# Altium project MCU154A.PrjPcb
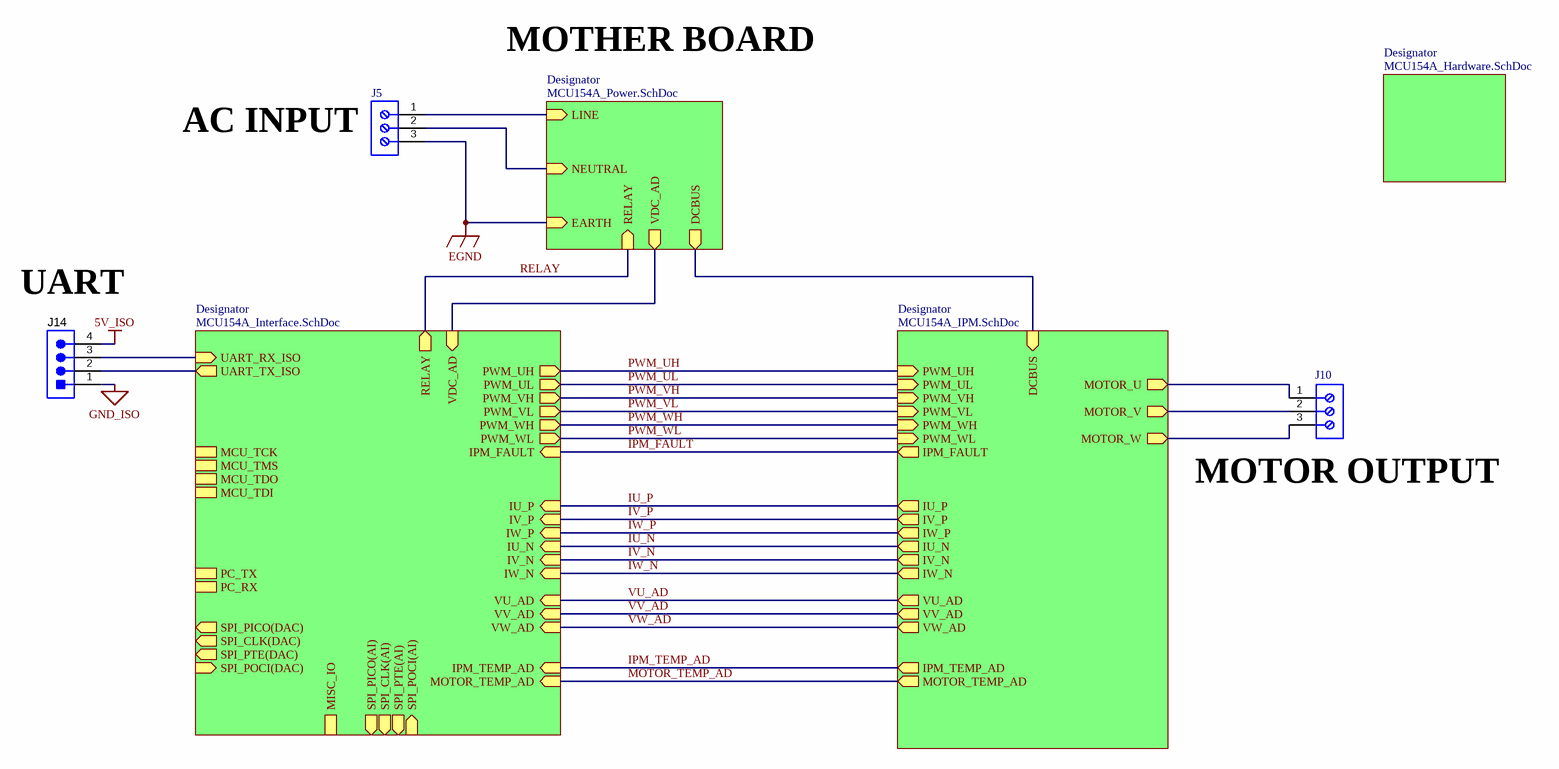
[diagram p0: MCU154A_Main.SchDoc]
CopyrightYear: 2024; EVM_orderable: TIEVM-MTR-HVIVN; Input_F: 50 Hz; Input_I: 8 A; Input_V: 230 VAC; Output_F_Motor: 200 Hz; Output_I: 3 A; Output_P: 750 W; Output_V: not available; PCB_Rev: A; PRJ_Customer: Public Release; PRJ_Engineer: Jason Osborn; PRJ_Number: MCU154; PRJ_Title: TIEVM-MTR-HVINV; SCH_Rev: A; TechSupport: http://www.ti.com/support; TID: TIDA-010265
5 sheets, 179 parts. Net scope: hierarchical (ports join the sheet entries above them; power ports are global).
Board file: MCU154A_PCB.PcbDoc
Sheets:
  MCU154A_Main.SchDoc
    Designator = MCU154A_Power.SchDoc
    Designator = MCU154A_IPM.SchDoc
    Designator = MCU154A_Interface.SchDoc
    Designator = MCU154A_Hardware.SchDoc

## Sheet MCU154A_Main.SchDoc: Main
size A3; Date: Not shown in title block; ApprovedBy: Not shown in title block; CheckedBy: Not shown in title block; Author: Not shown in title block; CompanyName: Not shown in title block; DrawnBy: Hely Zhang; Engineer: Not shown in title block; Organization: Not shown in title block; Address1: Not shown in title block; Address2: Not shown in title block; Address3: Not shown in title block; Address4: Not shown in title block; DocumentNumber: 1; Revision: Use project parameter SCH_Rev; SheetNumber: 1; SheetTotal: 5; PageSetup: Record=PageOptions¦CenterHorizontal=True¦CenterVertical=True¦PrintScale=0.93¦XCorrection=1.00¦YCorrection=1.00¦PrintKind=0¦BorderSize=5000000¦LeftOffset=0¦BottomOffset=0¦Orientation=2¦PaperLength=1000¦PaperWidth=1000¦Scale=100¦PaperSource=15¦PrintQuality=600¦MediaType=1¦DitherType=10¦PaperKind=Letter¦PrintScaleMode=1

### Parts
J5  691137710003  [691137710003]  (value not drawn)
J10  691137710003  [691137710003]  (value not drawn)
J14  70543-0038  [Molex_70543-0038]  (value not drawn)

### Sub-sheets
Designator = MCU154A_Power.SchDoc: RELAY (in), DCBUS (out), EARTH (in), LINE (in), NEUTRAL (in), VDC_AD (out)
Designator = MCU154A_IPM.SchDoc: MOTOR_U (out), MOTOR_V (out), VU_AD (out), VV_AD (out), VW_AD (out), PWM_UL (in), PWM_VH (in), PWM_VL (in), PWM_WH (in), PWM_WL (in), PWM_UH (in), IPM_FAULT (out), IW_P (out), IU_P (out), IV_P (out), MOTOR_TEMP_AD (out), DCBUS (in), MOTOR_W (out), IPM_TEMP_AD (out), IW_N (out), IU_N (out), IV_N (out)
Designator = MCU154A_Interface.SchDoc: PWM_UH (out), PWM_UL (out), PWM_VH (out), PWM_VL (out), PWM_WH (out), PWM_WL (out), RELAY (out), IV_P (in), IW_P (in), VU_AD (in), VV_AD (in), VW_AD (in), IPM_TEMP_AD (in), MOTOR_TEMP_AD (in), VDC_AD (in), SPI_PICO(DAC) (out), SPI_CLK(DAC) (out), SPI_POCI(DAC) (in), PC_RX, PC_TX, SPI_PTE(AI) (out), SPI_CLK(AI) (out), SPI_POCI(AI) (in), SPI_PICO(AI) (out), MCU_TCK, MCU_TMS, IPM_FAULT (in), IW_N (in), IU_N (in), IU_P (in), MISC_IO, IV_N (in), MCU_TDI, MCU_TDO, SPI_PTE(DAC) (out), UART_RX_ISO (in), UART_TX_ISO (out)
Designator = MCU154A_Hardware.SchDoc: no entries

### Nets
5V_ISO: J14.4
EGND: J5.3 ; sheet Designator/EARTH
GND_ISO: J14.1
Ubus: sheet Designator/DCBUS, sheet Designator/DCBUS
IPM_FAULT: sheet Designator/IPM_FAULT, sheet Designator/IPM_FAULT
IPM_TEMP_AD: sheet Designator/IPM_TEMP_AD, sheet Designator/IPM_TEMP_AD
IU_N: sheet Designator/IU_N, sheet Designator/IU_N
IU_P: sheet Designator/IU_P, sheet Designator/IU_P
IV_N: sheet Designator/IV_N, sheet Designator/IV_N
IV_P: sheet Designator/IV_P, sheet Designator/IV_P
IW_N: sheet Designator/IW_N, sheet Designator/IW_N
IW_P: sheet Designator/IW_P, sheet Designator/IW_P
LINE: J5.1 ; sheet Designator/LINE
MOTOR_TEMP_AD: sheet Designator/MOTOR_TEMP_AD, sheet Designator/MOTOR_TEMP_AD
MOTOR_U: J10.1 ; sheet Designator/MOTOR_U
MOTOR_V: J10.2 ; sheet Designator/MOTOR_V
MOTOR_W: J10.3 ; sheet Designator/MOTOR_W
NEU: J5.2 ; sheet Designator/NEUTRAL
PWM_UH: sheet Designator/PWM_UH, sheet Designator/PWM_UH
PWM_UL: sheet Designator/PWM_UL, sheet Designator/PWM_UL
PWM_VH: sheet Designator/PWM_VH, sheet Designator/PWM_VH
PWM_VL: sheet Designator/PWM_VL, sheet Designator/PWM_VL
PWM_WH: sheet Designator/PWM_WH, sheet Designator/PWM_WH
PWM_WL: sheet Designator/PWM_WL, sheet Designator/PWM_WL
RELAY: sheet Designator/RELAY, sheet Designator/RELAY
UART_RX_ISO: J14.3 ; sheet Designator/UART_RX_ISO
UART_TX_ISO: J14.2 ; sheet Designator/UART_TX_ISO
VDC_AD: sheet Designator/VDC_AD, sheet Designator/VDC_AD
VU_AD: sheet Designator/VU_AD, sheet Designator/VU_AD
VV_AD: sheet Designator/VV_AD, sheet Designator/VV_AD
VW_AD: sheet Designator/VW_AD, sheet Designator/VW_AD

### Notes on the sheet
- MOTHER BOARD
- AC INPUT
- (near J14) UART
- (near J10) MOTOR OUTPUT

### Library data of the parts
J5 J10 = CMP-1502-03325-2: NexarPartId: 78871138
J14 = CMP-0055267-1: Header(shrouded), 2.54mm, 4x1, Tin, TH; Manufacturer: Molex; CNHeader: FALSE; Shrouded: Y; Gender: Male; Row_Count: 1; Pitch_mm: 2.54

## Sheet MCU154A_Power.SchDoc: Power
size A4; Date: Not shown in title block; ApprovedBy: Not shown in title block; CheckedBy: Not shown in title block; Author: Not shown in title block; CompanyName: Not shown in title block; DrawnBy: Hely Zhang; Engineer: Not shown in title block; Organization: Not shown in title block; Address1: Not shown in title block; Address2: Not shown in title block; Address3: Not shown in title block; Address4: Not shown in title block; DocumentNumber: 1; Revision: Use project parameter SCH_Rev; SheetNumber: 2; SheetTotal: 5; PageSetup: Record=PageOptions¦CenterHorizontal=True¦CenterVertical=True¦PrintScale=0.93¦XCorrection=1.00¦YCorrection=1.00¦PrintKind=0¦BorderSize=5000000¦LeftOffset=0¦BottomOffset=0¦Orientation=2¦PaperLength=1000¦PaperWidth=1000¦Scale=100¦PaperSource=15¦PrintQuality=600¦MediaType=1¦DitherType=10¦PaperKind=Letter¦PrintScaleMode=1
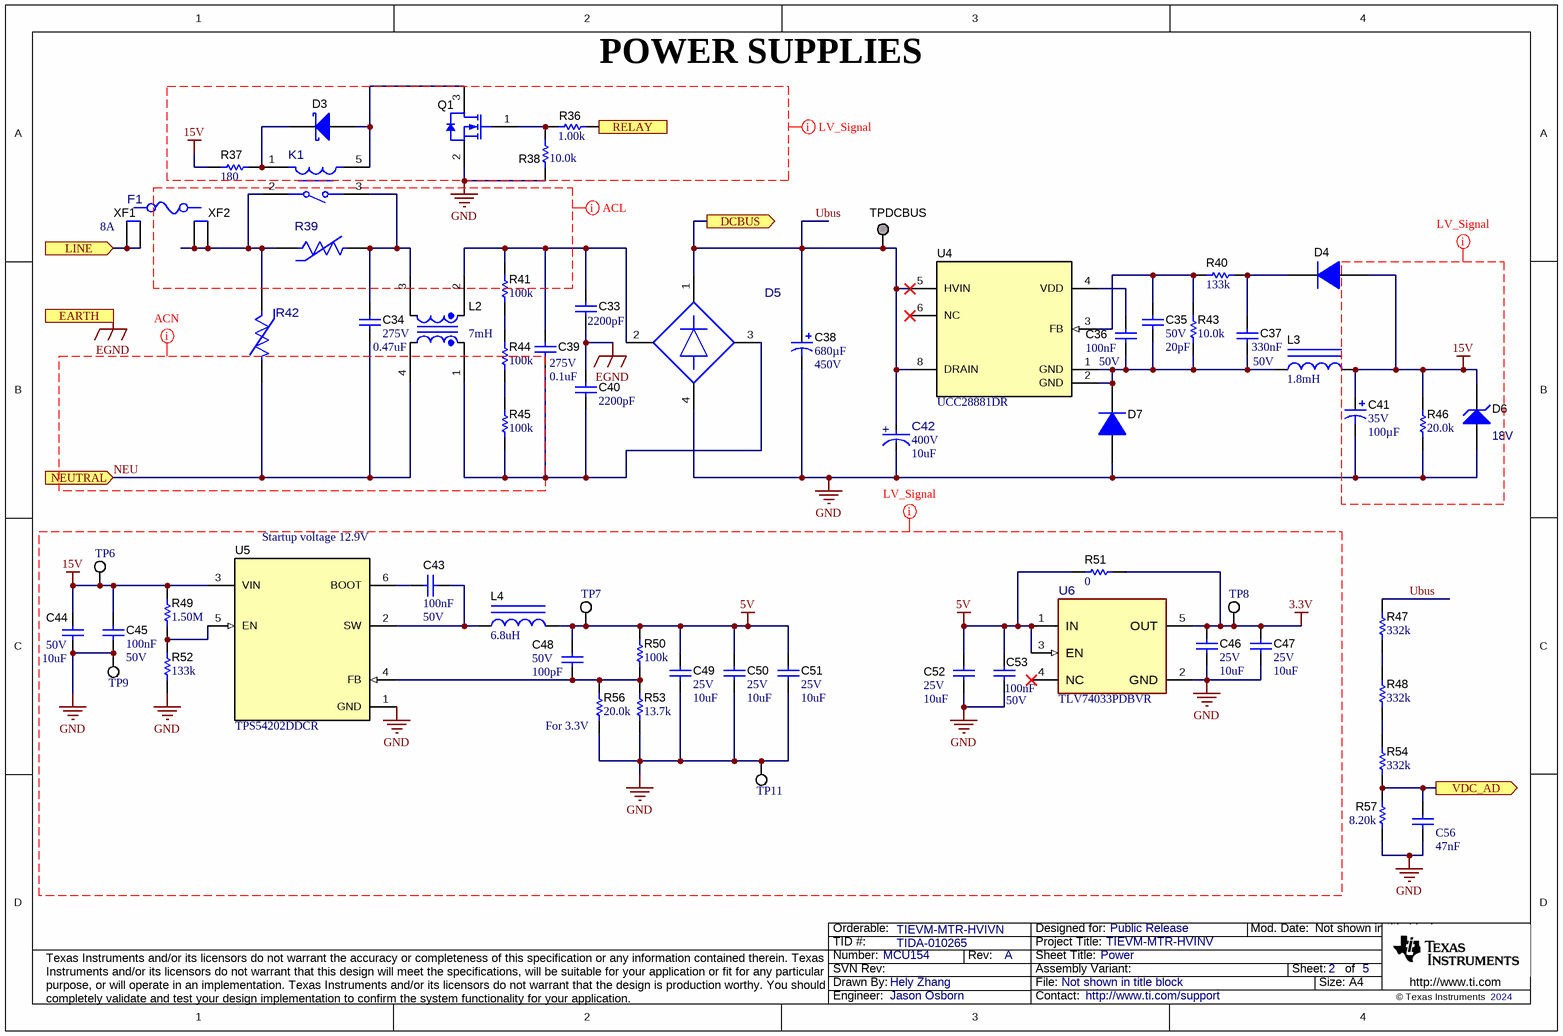
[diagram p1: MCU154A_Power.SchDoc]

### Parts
C33  ValueDisplayed: 2200pF  [KY_800x500x1100]  (hidden comment: DE2E3KY222MA2BM01F)
C34  VDC_V: 275V  ValueDisplayed: 0.47uF  [WCAP-FTX2_1500x1000x1600]  (hidden comment: 890324024005)
C35  VDC_V: 50V  ValueDisplayed: 20pF  [0603]  (hidden comment: GRM1885C1H200JA01D)
C36  Cap_F: 100nF  VDC_V: 50V  [0603]  (hidden comment: GCM188R71H104KA57D)
C37  Cap_F: 330nF  VDC_V: 50V  [0805_HV]  (hidden comment: GRM219R71H334KA88D)
C38  ValueDisplayed: 680µF  VDC_V: 450V  [WCAP-AI3H_3500x5700]  (hidden comment: 861141486026)
C39  VDC_V: 275V  ValueDisplayed: 0.1uF  [WCAP-FTX2_1800x600x1200]  (hidden comment: 890324025017)
C40  ValueDisplayed: 2200pF  [KY_800x500x1100]  (hidden comment: DE2E3KY222MA2BM01F)
C41  VDC_V: 35V  ValueDisplayed: 100µF  [Rubycon_630x1100]  (hidden comment: 35ZLJ100M6.3X11)
C42  VDC_V: 400V  ValueDisplayed: 10uF  [FP-860241375002_RADIAL-MFG]  (hidden comment: 860241375002)
C43  Cap_F: 100nF  VDC_V: 50V  [0603]  (hidden comment: GCM188R71H104KA57D)
C44  VDC_V: 50V  ValueDisplayed: 10uF  [1206_190]  (hidden comment: CL31A106KBHNNNE)
C45  Cap_F: 100nF  VDC_V: 50V  [0603]  (hidden comment: GCM188R71H104KA57D)
C46  VDC_V: 25V  ValueDisplayed: 10uF  [1206_180]  (hidden comment: GRM31CR71E106KA12L)
C47  VDC_V: 25V  ValueDisplayed: 10uF  [1206_180]  (hidden comment: GRM31CR71E106KA12L)
C48  VDC_V: 50V  ValueDisplayed: 100pF  [0603]  (hidden comment: GRM1885C1H101JA01D)
C49  VDC_V: 25V  ValueDisplayed: 10uF  [1206_180]  (hidden comment: GRM31CR71E106KA12L)
C50  VDC_V: 25V  ValueDisplayed: 10uF  [1206_180]  (hidden comment: GRM31CR71E106KA12L)
C51  VDC_V: 25V  ValueDisplayed: 10uF  [1206_180]  (hidden comment: GRM31CR71E106KA12L)
C52  VDC_V: 25V  ValueDisplayed: 10uF  [1206_180]  (hidden comment: GRM31CR71E106KA12L)
C53  Cap_F: 100nF  VDC_V: 50V  [0603]  (hidden comment: GCM188R71H104KA57D)
C56  Cap_F: 47nF  [WCAP-CSGP_0603_L1.6W0.8H0.8_Reflow]  (hidden comment: 885012206093)
D3  BAT54T1G  [SOD-123]  (value not drawn)
D4  US1M-13-F  [SMA]  (value not drawn)
D5  GBU15J  [FP-GBU8J_Horizontal_Face_Down_SIP4-MFG]  (value not drawn)
D6  value 18V  [SOD-323]  (hidden comment: MMSZ5248BS-7-F)
D7  US1M-13-F  [SMA]  (value not drawn)
F1  0215008.HXP  [FP-0215008.HXP_FUSE_CARTRIDGE-MFG]  (value not drawn)
K1  G5Q-1A4-EU DC12  [FP-G5Q-1A4-EU DC12_PTH_RELAY_20MM0_10MM0-MFG]  (value not drawn)
L2  ValueDisplayed: 7mH  [WE-CMBNC_L]  (hidden comment: 7448040707)
L3  ValueDisplayed: 1.8mH  [WE-TI_8095]  (hidden comment: 768772182)
L4  ValueDisplayed: 6.8uH  [WE-MAIA_3015]  (hidden comment: 78438335068)
Q1  2N7002P,215  [SOT-23]  (value not drawn)
R36  ValueDisplayed: 1.00k  [0603]  (hidden comment: RC0603FR-071KL)
R37  ValueDisplayed: 180  [1210]  (hidden comment: RC1210FR-07180RL)
R38  ValueDisplayed: 10.0k  [0603]  (hidden comment: RC0603FR-0710KL)
R39  B59770C0120A070  [FP-B59770C0120A070_RADIAL-MFG]  (value not drawn)
R40  ValueDisplayed: 133k  [0603]  (hidden comment: RC0603FR-07133KL)
R41  ValueDisplayed: 100k  [1206]  (hidden comment: RC1206FR-07100KL)
R42  IsoM3-275-B-L2  [FP-IsoM3-275-B-L2_RADIAL-MFG]  (value not drawn)
R43  ValueDisplayed: 10.0k  [0603]  (hidden comment: RC0603FR-0710KL)
R44  ValueDisplayed: 100k  [1206]  (hidden comment: RC1206FR-07100KL)
R45  ValueDisplayed: 100k  [1206]  (hidden comment: RC1206FR-07100KL)
R46  ValueDisplayed: 20.0k  [0603]  (hidden comment: RC0603FR-0720KL)
R47  ValueDisplayed: 332k  [1206]  (hidden comment: RC1206FR-07332KL)
R48  ValueDisplayed: 332k  [1206]  (hidden comment: RC1206FR-07332KL)
R49  ValueDisplayed: 1.50M  [0603]  (hidden comment: RC0603FR-071M5L)
R50  ValueDisplayed: 100k  [0603]  (hidden comment: RC0603FR-07100KL)
R51  ValueDisplayed: 0  [0603]  (hidden comment: RC0603JR-070RL)
R52  ValueDisplayed: 133k  [0603]  (hidden comment: RC0603FR-07133KL)
R53  ValueDisplayed: 13.7k  [0603]  (hidden comment: RC0603FR-0713K7L)
R54  ValueDisplayed: 332k  [1206]  (hidden comment: RC1206FR-07332KL)
R56  ValueDisplayed: 20.0k  [0603]  (hidden comment: RC0603FR-0720KL)
R57  ValueDisplayed: 8.20k  [0603]  (hidden comment: RC0603FR-078K2L)
TP6  5015  [Testpoint_Keystone_Miniature]  (value not drawn)
TP7  5015  [Testpoint_Keystone_Miniature]  (value not drawn)
TP8  5015  [Testpoint_Keystone_Miniature]  (value not drawn)
TP9  5015  [Testpoint_Keystone_Miniature]  (value not drawn)
TP11  5015  [Testpoint_Keystone_Miniature]  (value not drawn)
TPDCBUS  TP_SM_1MM  [TP_SM_1MM]  (value not drawn)  (no BOM)
U4  UCC28881DR  [D0007A_N]
U5  TPS54202DDCR  [DDC0006A_N]
U6  TLV74033PDBVR  [DBV0005A-MFG]
XF1  01000056Z  [Littelfuse_0100-0020_54_56]  (value not drawn)
XF2  01000056Z  [Littelfuse_0100-0020_54_56]  (value not drawn)

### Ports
DCBUS (out), EARTH (in), LINE (in), NEUTRAL (in), RELAY (in), VDC_AD (out)

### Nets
3.3V: C46.1 C47.1 R51.2 TP8.1 U6.5(OUT)
5V: C48.1 C49.1 C50.1 C51.1 C52.1 C53.1 L4.2 R50.2 R51.1 TP7.1 U6.1(IN) U6.3(EN)
15V: C41.1(+) C44.1 C45.1 D4.2(A) D6.1(K) L3.2 R37.1 R46.2 R49.2 TP6.1 U5.3(VIN)
EGND: C33.2 C40.1 ; port EARTH
GND: C38.2(-) C41.2(-) C42.1(CATHODE) C44.2 C45.2 C46.2 C47.2 C49.2 C50.2 C51.2 C52.2 C53.2 C56.1 D5.4(-) D6.2(A) D7.2(A) Q1.2(S) R38.1 R46.1 R52.1 R53.1 R56.1 R57.1 TP9.1 TP11.1 U5.1(GND) U6.2(GND)
Ubus: C38.1(+) C42.2(ANODE) D5.1(+) R47.2 TPDCBUS.1 U4.5(HVIN) U4.8(DRAIN) ; port DCBUS
LINE: XF1.1 XF1.2 ; port LINE
NEU: C34.2 L2.4 R42.1 ; port NEUTRAL
RELAY: R36.1 ; port RELAY
VDC_AD: C56.2 R54.1 R57.2 ; port VDC_AD
NetC33_1: C33.1 C39.1 D5.2(1_~) L2.2 R41.2
NetC34_1: C34.1 K1.3 L2.3 R39.2
NetC35_1: C35.1 R40.1 R43.2 U4.3(FB)
NetC35_2: C35.2 C36.2 C37.2 D7.1(K) L3.1 R43.1 U4.1(GND) U4.2(GND)
NetC36_1: C36.1 U4.4(VDD)
NetC37_1: C37.1 D4.1(K) R40.2
NetC39_2: C39.2 C40.2 D5.3(2_~) L2.1 R45.1
NetC43_1: C43.1 U5.6(BOOT)
NetC43_2: C43.2 L4.1 U5.2(SW)
NetC48_2: C48.2 R50.1 R53.2 R56.2 U5.4(FB)
NetD3_1: D3.1(K) K1.1 R37.2
NetD3_2: D3.2(A) K1.5 Q1.3(D)
NetK1_2: K1.2 R39.1 R42.2 XF2.1 XF2.2
NetQ1_1: Q1.1(G) R36.2 R38.2
NetR41_1: R41.1 R44.2
NetR44_1: R44.1 R45.2
NetR47_1: R47.1 R48.2
NetR48_1: R48.1 R54.2
NetR49_1: R49.1 R52.2 U5.5(EN)

Not connected (* = marked no-connect by the designer): U4 6(NC)*; U6 4(NC)*

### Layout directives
net class ACN: NEU
net class LV_Signal: 3.3V, 5V, 15V, GND
net class ACL: (no net found under the mark)

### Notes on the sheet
- POWER SUPPLIES
- (near XF1) 8A
- Startup voltage 12.9V
- (near R56) For 3.3V

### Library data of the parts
C33 C40 = CMP-0067532-1: CAP, CERM, 2200 pF, X1 250 VAC/Y2 250 VAC, +/- 20%, E, 8x5mm; Manufacturer: MuRata; TaMin_C: -40°C; AC_Safety: X1Y2; Polarized: N; SizeAreaWB_mm2: 70.0; Value1: Unknown; U/M: EA; Value: 2200pF; TaMax_C: 125°C; VAC_X: 250; SizeZ_mm: 11.0; SizeX_mm: 8.0; SizeY_mm: 5.0; Cap_Case: 8x5x11mm; Value2: V; SizeArea_mm2: 40.0; Cap_F: 2.2nF; AEC Category: Q200
C34 = CMP-0012313-1: CAP, Film, 0.47 uF, 275 V, +/- 10%, TH; Manufacturer: Wurth Elektronik; TaMin_C: -40°C; Polarized: N; SizeAreaWB_mm2: 204; Value1: Unknown; U/M: EA; Value: 0.47uF; TaMax_C: 105°C; SizeZ_mm: 16.5; SizeX_mm: 15; SizeY_mm: 10; Cap_Case: 15x10x16mm; SizeArea_mm2: 150; Cap_F: 470nF; AEC Category: Q200
C35 = CMP-0007193-4: CAP, CERM, 20 pF, 50 V, +/- 5%, C0G/NP0, 0603; Manufacturer: MuRata; TaMin_C: -55°C; Polarized: N; SizeAreaWB_mm2: 4.68; Value1: Unknown; U/M: EA; Value: 20pF; TaMax_C: 125°C; SizeZ_mm: 1; SizeX_mm: 1.6; SizeY_mm: 0.8; SizeArea_mm2: 1.28; AEC Category: Q200
C36 C43 C45 C53 = CMP-0007144-4: CAP, CERM, 0.1 uF, 50 V, +/- 10%, X7R, 0603; Manufacturer: MuRata; TaMin_C: -55°C; ESR_ohm: 20m; Polarized: N; SizeAreaWB_mm2: 4.68; Value1: 0.02 ohm; U/M: EA; Value: 0.1uF; TaMax_C: 125°C; SizeZ_mm: 1; SizeX_mm: 1.6; SizeY_mm: 0.8; SizeArea_mm2: 1.28; IRMS_A: 1.84A; AEC Category: Q200
C37 = CMP-0008227-2: CAP, CERM, 0.33 uF, 50 V, +/- 10%, X7R, 0805; Manufacturer: MuRata; TaMin_C: -55°C; Polarized: N; SizeAreaWB_mm2: 6.75; Value1: Unknown; U/M: EA; Value: 0.33uF; TaMax_C: 125°C; SizeZ_mm: 1.45; SizeX_mm: 2; SizeY_mm: 1.25; Cap_Case: 0805; SizeArea_mm2: 2.5; AEC Category: Q200
C38 = CMP-0084882-1: CAP, AL, 680 µF, 450 V, +/- 20%, TH; Manufacturer: Wurth Elektronik; SizeY_mm: 35; CompType: Capacitor; U/M: EA; SizeZ_mm: 59; SizeAreaWB_mm2: 1369; SizeArea_mm2: 1225; TaMax_C: 105°C; AEC Category: Q200; Cap_Case: 35x57mm; TaMin_C: -25°C; AEC Qualified: N; Value: 680uF; Polarized: Y
C39 = CMP-0012314-3: CAP, Film, 0.1 uF, 275 V, +/- 10%, TH; Manufacturer: Wurth Elektronik; TaMin_C: -40°C; Polarized: N; Value1: Unknown; Value: 0.1uF; TaMax_C: 105°C; Cap_Case: 18x6x12mm; Cap_F: 100nF; AEC Category: Q200
C41 = CMP-0080807-1: CAP, AL, 100 µF, 35 V, +/- 20%, TH; Manufacturer: Rubycon; IRMS_A: 700mA; SizeAreaWB_mm2: 68.89; SizeArea_mm2: 39.69; AEC Qualified: N; AEC Category: Q200; Value: 100uF; TaMax_C: 105°C; SizeZ_mm: 12.5; Polarized: Y; TaMin_C: -40°C; SizeY_mm: 6.3; U/M: EA; CompType: Capacitor; Cap_Case: 6.3x11
C42 = CMP-0096475-1: 10 µF 400 V Aluminum Electrolytic Capacitors Radial, Can 10000 Hrs @ 105°C; Manufacturer: Wurth Electronics; Leakage Current: 260uA; Life: 10000Hours; IRMS_A: 274mA; Tolerance_%: 20%; AEC Qualified: No; Value: 10µF; SizeZ_mm: 17.5mm
C44 = CMP-0008799-2: CAP, CERM, 10 uF, 50 V, +/- 10%, X5R, 1206_190; Manufacturer: Samsung Electro-Mechanics; TaMin_C: -55°C; Polarized: N; SizeAreaWB_mm2: 10.92; Value1: Unknown; U/M: EA; Value: 10uF; TaMax_C: 85°C; SizeZ_mm: 1.9; SizeX_mm: 3.2; SizeY_mm: 1.6; Cap_Case: 1206; SizeArea_mm2: 5.12; Cap_F: 10µF; AEC Category: Q200
C46 C47 C49-C52 = CMP-0008965-2: CAP, CERM, 10 uF, 25 V, +/- 10%, X7R, 1206; Manufacturer: MuRata; TaMin_C: -55°C; Polarized: N; SizeAreaWB_mm2: 10.92; Value1: Unknown; U/M: EA; Value: 10uF; TaMax_C: 125°C; SizeZ_mm: 1.8; SizeX_mm: 3.2; SizeY_mm: 1.6; Cap_Case: 2220; SizeArea_mm2: 5.12; Cap_F: 10µF; AEC Category: Q200
C48 = CMP-0007171-4: CAP, CERM, 100 pF, 50 V, +/- 5%, C0G/NP0, 0603; Manufacturer: MuRata; TaMin_C: -55°C; Polarized: N; SizeAreaWB_mm2: 4.68; Value1: Unknown; U/M: EA; Value: 100pF; TaMax_C: 125°C; SizeZ_mm: 1; SizeX_mm: 1.6; SizeY_mm: 0.8; SizeArea_mm2: 1.28; AEC Category: Q200
C56 = CMP-0115476-1: WCAP-CSGP Multilayer Ceramic Chip Capacitor, General Purpose, size 0603, X7R, 47nF, 50VDC; Manufacturer: Wurth Elektronik; Capacitance Tolerance: +/-10%; Case/Size Code: 0603; Dissipation Factor: 3%; Insulation Resistance: 10GOhm; Rated Voltage (DC): 50V; Technical Reference: X7R0603473K050DFCT10000
D3 = CMP-0028457-2: Diode, Schottky, 30 V, 0.2 A, SOD-123; Manufacturer: ON Semiconductor; SizeArea_mm2: 6.545; Io_A: 200mA; SizeX_mm: 3.85; Value1: 0.2A; SizeY_mm: 1.7; AEC Category: Q101; Vf_V: 800mV; TJmax_C: 125°C; Green_Lifecycle: Not Set; RJC_CperW: 174; Value: 30V; Value2: 0.8V; SizeAreaWB_mm2: 13.095; Green_REACh: Incomplete; SizeZ_mm: 1.35
D4 D7 = CMP-0076882-1: Diode, Ultrafast, 1000 V, 1 A, SMA; Manufacturer: Diodes Inc.; SizeAreaWB_mm2: 37.3428; Vr_V: 1kV; SizeArea_mm2: 16.3228; TJmax_C: 150°C; AEC Category: Q101; Value: 1000V; SizeZ_mm: 2.87; Green_REACh: Incomplete; Io_A: 1A; Vf_V: 1.7V; SizeY_mm: 2.92; Green_Lifecycle: Not Set; U/M: EA; SizeX_mm: 5.59; RJC_CperW: 30.0
D5 = CMP-0096899-4: Bridge Rectifier Single Phase Standard 600 V Through Hole GBU; PartNumber: GBU8J; Manufacturer: Diotec; Standoff Height: 1.6mm; SizeZ_mm: 21.2mm; Vf_V: 600V; TJmax_C: 150°C; Forward Current: 5.6A; AEC Qualified: No; CompType: Diode; AEC Category: Q101; ValueDisplayed: 80pF; Peak Reverse Current: 5uA; Max Surge Forward Current: 180A
D6 = CMP-0005835-4: Diode, Zener, 18 V, 200 mW, SOD-323; Manufacturer: Diodes Inc.; Value1: 0.2W; SizeArea_mm2: 3.645; AEC Category: Q101; Power_W: 200mW; SizeAreaWB_mm2: 8.695; SizeY_mm: 1.35; RJA_CperW: 350; SizeZ_mm: 1; SizeX_mm: 2.7
F1 = CMP-0097018-1: Fuse Miniature Slow Blow Acting 8A 250V Holder Cartridge 5 X 20mm Ceramic Bulk; Manufacturer: Littelfuse Inc; AEC Qualified: No; Res_ohm: 0.0092Ω; Interrupt_AC: 1.5kA; MeltingTyp: 209.88A2Sec; SizeZ_mm: 5.3mm; Fuse Voltage Drop: 100mV
K1 = CMP-0096783-1: Electromechanical Relay SPST-NO 5(NO)/3(NC)ADC/10(NO)/3(NC)AAC 12VDC 720Ohm Through Hole; Manufacturer: Omron; SizeZ_mm: 16.2mm; Standoff Height: 0.4mm; Coil Current_A: 16.7mA; Coil Power_W: 200mW; Coil Resistance: 720Ω; Coil Voltage_VDC: 12V; TaMin_C: -40°C; Switching Current: 3/5A; Contact Rating_A: 10A; Coil Type: Non-Latching; TaMax_C: +85°C
L2 = CMP-0013082-2: Coupled inductor, 7 mH, 7 A, 0.02 ohm, TH; Manufacturer: Wurth Elektronik; Value: 7mH; DCR_ohm: 0.02
L3 = CMP-0064862-2: Inductor, Shielded Drum Core, Metal Composite, 1.8 mH, 0.35 A, 2.7 ohm, TH; Manufacturer: Wurth Elektronik; Isat: 0.38A @ 10% inductance drop; Irms: 0.35A @ 40C rise; Green_Lifecycle: Active; SizeAreaWB_mm2: 96.04; DCR_ohm: 2.7; Green_REACh: Passed; Value1: 2.7 ohm; Value: 1.8mH; Imax_A: 350mA; SizeZ_mm: 10; SizeX_mm: 7.8; Value2: 0.35A; SizeArea_mm2: 60.84; AEC Category: Q200
L4 = CMP-0064362-1: Inductor, Shielded, Powdered Iron, 6.8 uH, 1.1 A, 0.287 ohm, AEC-Q200 Grade 1, SMD; Manufacturer: Wurth Elektronik; Isat: 2.4A @ 20% inductance drop; Irms: 1.1A @ 40C rise; SizeAreaWB_mm2: 16; DCR_ohm: 0.287; Value: 6.8uH; Imax_A: 1.1A; SizeZ_mm: 1.5; SizeX_mm: 3; SizeArea_mm2: 9; Ind_H: 6.8µH; AEC Qualified: Y; AEC Grade: 1; AEC Category: Q200
Q1 = CMP-0000775-2: MOSFET, N-CH, 60 V, 0.36 A, SOT-23; Alternate Manufacturer: None; Manufacturer: Nexperia; SizeZ_mm: 1.1; ChType: N; Value2: 0.6 nC; VdsMax_V: 60V; SizeX_mm: 2.5; SizeY_mm: 3; Vgs_V: 20V; Value: 60V; Rdson45_ohm: 2; SizeArea_mm2: 7.5; AEC Category: Q101; IdsMax_A: 360mA; SizeAreaWB_mm2: 14; QgTyp_nC: 0.6
R36 = CMP-0022895-5: RES, 1.00 k, 1%, 0.1 W, 0603; Manufacturer: Yageo; Power_W: 100mW; TempCo: 100 ppm/C; Value_Code: 1k00; Value: 1.00k; EIA_Code: E96; Res_ohm: 1k; SizeX_mm: 1.6; SizeY_mm: 0.8; SizeZ_mm: 1; Value2: 0.1W; SizeArea_mm2: 1.28; AEC Qualified: N; VDC_V: 75V; AEC Category: Q200; SizeAreaWB_mm2: 4.68
R37 = CMP-0082820-1: RES, 180, 1%, 0.5 W, 1210; Manufacturer: Yageo; Power_W: 500mW; TempCo: 100 ppm/C; SizeAreaWB_mm2: 14.7; Value_Code: 180R; Value: 180; SizeX_mm: 3.2; SizeY_mm: 2.5; SizeZ_mm: 1.35; Value2: 0.5W; SizeArea_mm2: 8; AEC Qualified: N; VDC_V: 200V; AEC Category: Q200
R38 R43 = CMP-0022746-5: RES, 10.0 k, 1%, 0.1 W, 0603; Manufacturer: Yageo; Power_W: 100mW; TempCo: 100 ppm/C; Value_Code: 10k0; Value: 10.0k; EIA_Code: E96; Res_ohm: 10k; SizeX_mm: 1.6; SizeY_mm: 0.8; SizeZ_mm: 1; Value2: 0.1W; SizeArea_mm2: 1.28; AEC Qualified: N; VDC_V: 75V; AEC Category: Q200; SizeAreaWB_mm2: 4.68
R39 = CMP-0096764-1: PTC Thermistor 70 Ohms Disc, 13mm Dia x 7.5mm W; Manufacturer: TDK; AEC Qualified: No; Tolerance_%: 25%; Value: 70Ω; SizeZ_mm: 13.5mm; VDC_V: 370V
R40 R52 = CMP-0022786-4: RES, 133 k, 1%, 0.1 W, 0603; Manufacturer: Yageo; Power_W: 100mW; TempCo: 100 ppm/C; Value: 133k; EIA_Code: E96; SizeX_mm: 1.6; SizeY_mm: 0.8; SizeZ_mm: 1; Value2: 0.1W; SizeArea_mm2: 1.28; AEC Qualified: N; VDC_V: 75V; AEC Category: Q200; SizeAreaWB_mm2: 4.68
R41 R44 R45 = CMP-0017836-1: RES, 100 k, 1%, 0.25 W, 1206; Manufacturer: Yageo America; Power_W: 250mW; TempCo: 100 ppm/C; U/M: EA; Value: 100k; EIA_Code: E96; SizeX_mm: 3.2; SizeY_mm: 1.6; SizeZ_mm: 1.35; Value2: 0.25W; SizeArea_mm2: 5.12; VDC_V: 200V; AEC Category: Q200
R42 = CMP-0097027-1: 3 kA Varistor 1 Circuit Through Hole Disc 13.2mm; Manufacturer: Bourns; VDC_V: 350V; Vc: 50A; Cap_F: 30pF; AEC Qualified: No; Clamping Voltage: 730V; SizeZ_mm: 19mm
R46 R56 = CMP-0022906-5: RES, 20.0 k, 1%, 0.1 W, 0603; Manufacturer: Yageo; Power_W: 100mW; TempCo: 100 ppm/C; Value_Code: 20k0; Value: 20.0k; EIA_Code: E96; Res_ohm: 20k; SizeX_mm: 1.6; SizeY_mm: 0.8; SizeZ_mm: 1; Value2: 0.1W; SizeArea_mm2: 1.28; AEC Qualified: N; VDC_V: 75V; AEC Category: Q200; SizeAreaWB_mm2: 4.68
R47 R48 R54 = CMP-0018207-2: RES, 332 k, 1%, 0.25 W, 1206; Manufacturer: Yageo America; Power_W: 250mW; TempCo: 100 ppm/C; U/M: EA; Value: 332k; EIA_Code: E96; SizeX_mm: 3.2; SizeY_mm: 1.6; SizeZ_mm: 1.35; Value2: 0.25W; SizeArea_mm2: 5.12; VDC_V: 200V; AEC Category: Q200
R49 = CMP-0022898-4: RES, 1.50 M, 1%, 0.1 W, 0603; Manufacturer: Yageo; Power_W: 100mW; TempCo: 100 ppm/C; Value_Code: 1M50; Value: 1.50Meg; EIA_Code: E96; Res_ohm: 1.5M; SizeX_mm: 1.6; SizeY_mm: 0.8; SizeZ_mm: 1; Value2: 0.1W; SizeArea_mm2: 1.28; AEC Qualified: N; VDC_V: 75V; AEC Category: Q200; SizeAreaWB_mm2: 4.68
R50 = CMP-0022735-5: RES, 100 k, 1%, 0.1 W, 0603; Manufacturer: Yageo; Power_W: 100mW; TempCo: 100 ppm/C; Value: 100k; EIA_Code: E96; SizeX_mm: 1.6; SizeY_mm: 0.8; SizeZ_mm: 1; Value2: 0.1W; SizeArea_mm2: 1.28; AEC Qualified: N; VDC_V: 75V; AEC Category: Q200; SizeAreaWB_mm2: 4.68
R51 = CMP-0025885-5: RES, 0, 5%, 0.1 W, 0603; Manufacturer: Yageo; Power_W: 100mW; TempCo: 200 ppm/C; Value_Code: 0000; Value: 0; EIA_Code: E24; SizeX_mm: 1.6; SizeZ_mm: 1; Value2: 0.1W; SizeArea_mm2: 1.28; AEC Qualified: N; VDC_V: 75V; AEC Category: Q200; SizeY_mm: 0.8; SizeAreaWB_mm2: 4.68
R53 = CMP-0022791-5: RES, 13.7 k, 1%, 0.1 W, 0603; Manufacturer: Yageo; Power_W: 100mW; TempCo: 100 ppm/C; Value_Code: 13k7; Value: 13.7k; EIA_Code: E96; SizeX_mm: 1.6; SizeY_mm: 0.8; SizeZ_mm: 1; Value2: 0.1W; SizeArea_mm2: 1.28; AEC Qualified: N; VDC_V: 75V; AEC Category: Q200; SizeAreaWB_mm2: 4.68
R57 = CMP-0023308-5: RES, 8.20 k, 1%, 0.1 W, 0603; Manufacturer: Yageo; Power_W: 100mW; TempCo: 100 ppm/C; Value_Code: 8k20; Value: 8.20k; Res_ohm: 8.2k; SizeX_mm: 1.6; SizeY_mm: 0.8; SizeZ_mm: 1; Value2: 0.1W; SizeArea_mm2: 1.28; AEC Qualified: N; VDC_V: 75V; AEC Category: Q200; SizeAreaWB_mm2: 4.68
TP6-TP9 TP11 = CMP-0055152-2: Test Point, Miniature, SMT; Manufacturer: Keystone Electronics; CT: TRUE; Green_Lifecycle: Active; Green_REACh: Passed; CNHeader: FALSE
TPDCBUS = CMP-0003825-1: 1mm Test Point, SMT; Manufacturer: Any
U4 = CMP-0074092-1: 700-V Lowest Quiescent Current Off-Line Switcher, D0007A (SOIC-7); Alternate Manufacturer: Texas Instruments; SizeAreaWB_mm2: 55.2; U/M: EA; SizeZ_mm: 1.75; SizeX_mm: 6.0; SizeY_mm: 4.9; SizeArea_mm2: 29.4; CompType: IC
U5 = CMP-0073969-3: 4.5V to 28V Input, 2A Output, EMI Friendly Synchronous Step-Down Converter, DDC0006A (SOT-23-THIN-6); Alternate PartNumber: TPS54202DDCT; Manufacturer: Texas Instruments; SizeZ_mm: 0.87; SizeX_mm: 1.65; SizeY_mm: 2.95; SizeArea_mm2: 4.8675; CompType: IC; SizeAreaWB_mm2: 10.4675; AEC Category: Q200; AEC Qualified: N; Rating: Catalog
U6 = CMP-0090171-1: 300-mA low-dropout (LDO) regulator with foldback current limit 5-SOT-23 -40 to 125; Manufacturer: Texas Instruments; SizeZ_mm: 1.45mm; Output Type: Fixed; Nominal Supply Current: 50uA; TJmax_C: +85°C; Max Supply Voltage: 5.5V; Standoff Height: 0mm; AEC Qualified: No; Accuracy Percentage: 1%; Output Voltage: 3.3V; Number Of Outputs: 1; Dropout Voltage: 460mV
XF1 XF2 = CMP-0003676-1: Fuse Holder, 10A, TH; Manufacturer: Littelfuse

## Sheet MCU154A_IPM.SchDoc: IPM
size Letter; Date: Not shown in title block; ApprovedBy: Not shown in title block; CheckedBy: Not shown in title block; Author: Not shown in title block; CompanyName: Not shown in title block; DrawnBy: Hely Zhang; Engineer: Not shown in title block; Organization: Not shown in title block; Address1: Not shown in title block; Address2: Not shown in title block; Address3: Not shown in title block; Address4: Not shown in title block; DocumentNumber: 1; Revision: Use project parameter SCH_Rev; SheetNumber: 3; SheetTotal: 5; PageSetup: Record=PageOptions¦CenterHorizontal=True¦CenterVertical=True¦PrintScale=0.97¦XCorrection=1.00¦YCorrection=1.00¦PrintKind=0¦BorderSize=5000000¦LeftOffset=0¦BottomOffset=0¦Orientation=2¦PaperLength=1000¦PaperWidth=1000¦Scale=100¦PaperSource=15¦PrintQuality=600¦MediaType=1¦DitherType=10¦PaperKind=Letter¦PrintScaleMode=1
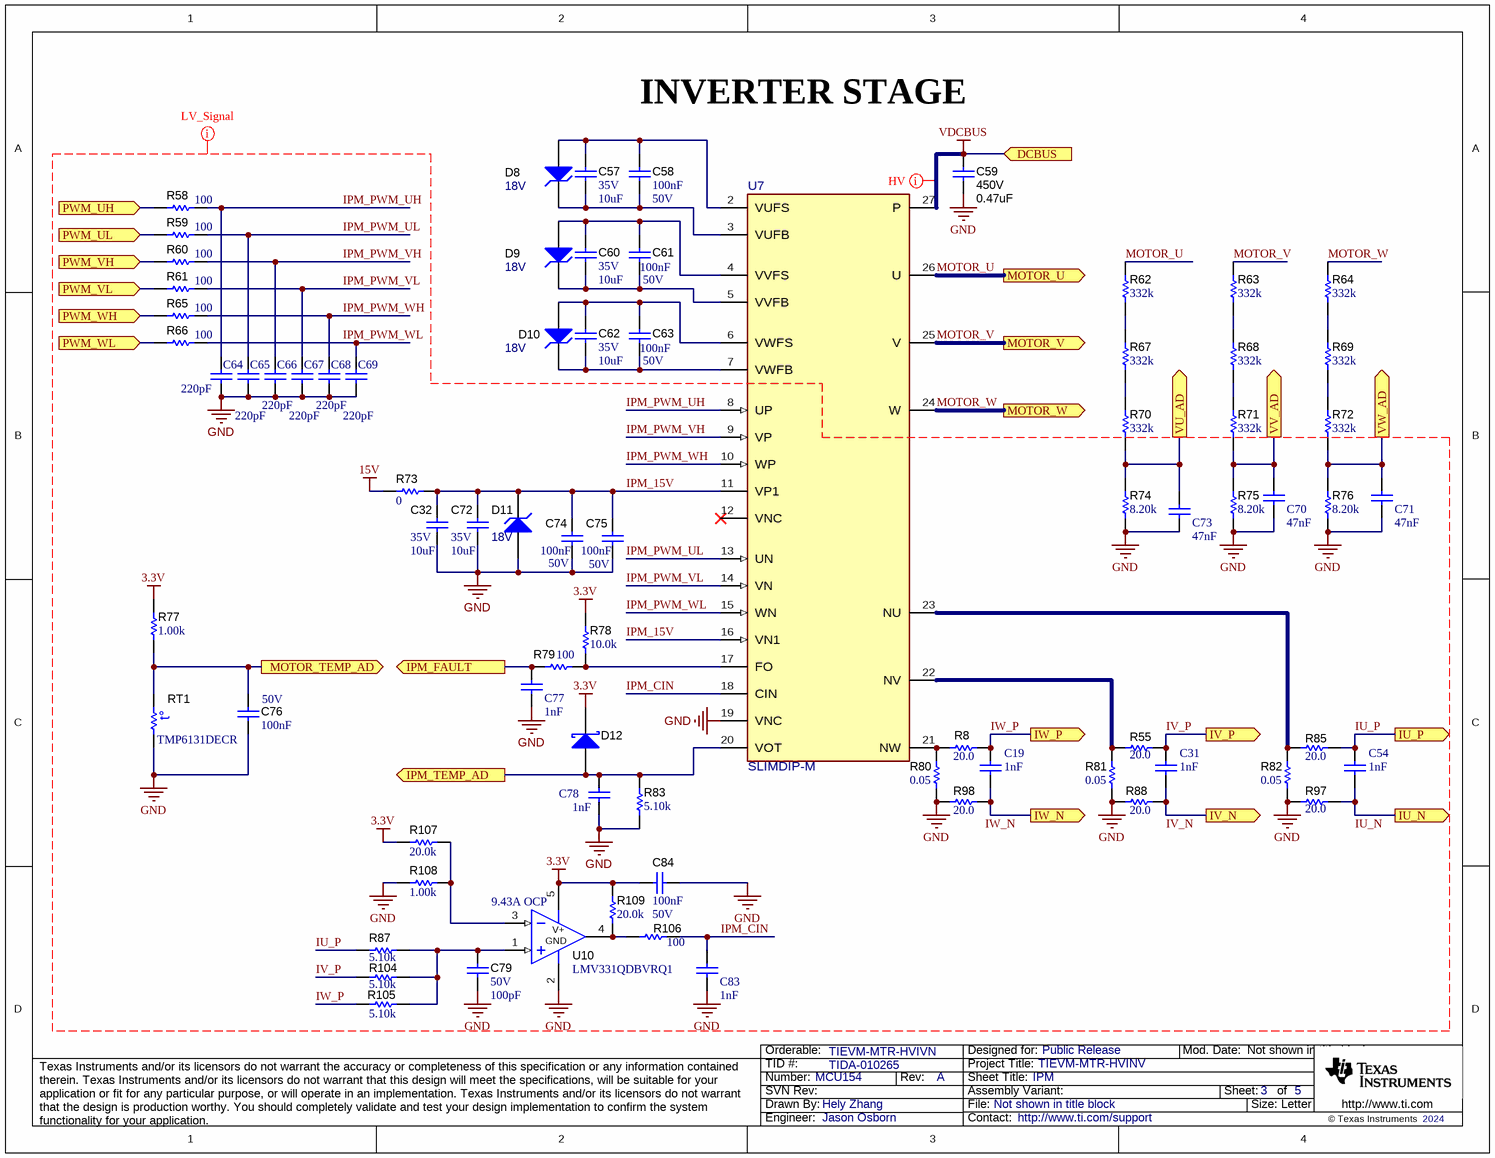
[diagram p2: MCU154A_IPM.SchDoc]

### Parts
C19  Cap_F: 1nF  [WCAP-CSGP_0603_L1.6W0.8H0.8_Reflow]  (hidden comment: 885012206059)
C31  Cap_F: 1nF  [WCAP-CSGP_0603_L1.6W0.8H0.8_Reflow]  (hidden comment: 885012206059)
C32  VDC_V: 35V  ValueDisplayed: 10uF  [0805_HV]  (hidden comment: GRM21BR6YA106KE43L)
C54  Cap_F: 1nF  [WCAP-CSGP_0603_L1.6W0.8H0.8_Reflow]  (hidden comment: 885012206059)
C57  VDC_V: 35V  ValueDisplayed: 10uF  [0805_HV]  (hidden comment: GRM21BR6YA106KE43L)
C58  Cap_F: 100nF  VDC_V: 50V  [0603]  (hidden comment: GCM188R71H104KA57D)
C59  VDC_V: 450V  ValueDisplayed: 0.47uF  [ECWFD_1260x650x1270]  (hidden comment: ECW-FD2W474Q1)
C60  VDC_V: 35V  ValueDisplayed: 10uF  [0805_HV]  (hidden comment: GRM21BR6YA106KE43L)
C61  Cap_F: 100nF  VDC_V: 50V  [0603]  (hidden comment: GCM188R71H104KA57D)
C62  VDC_V: 35V  ValueDisplayed: 10uF  [0805_HV]  (hidden comment: GRM21BR6YA106KE43L)
C63  Cap_F: 100nF  VDC_V: 50V  [0603]  (hidden comment: GCM188R71H104KA57D)
C64  Cap_F: 220pF  [WCAP-CSGP_0603_L1.6W0.8H0.8_Reflow]  (hidden comment: 885012206079)
C65  Cap_F: 220pF  [WCAP-CSGP_0603_L1.6W0.8H0.8_Reflow]  (hidden comment: 885012206079)
C66  Cap_F: 220pF  [WCAP-CSGP_0603_L1.6W0.8H0.8_Reflow]  (hidden comment: 885012206079)
C67  Cap_F: 220pF  [WCAP-CSGP_0603_L1.6W0.8H0.8_Reflow]  (hidden comment: 885012206079)
C68  Cap_F: 220pF  [WCAP-CSGP_0603_L1.6W0.8H0.8_Reflow]  (hidden comment: 885012206079)
C69  Cap_F: 220pF  [WCAP-CSGP_0603_L1.6W0.8H0.8_Reflow]  (hidden comment: 885012206079)
C70  Cap_F: 47nF  [WCAP-CSGP_0603_L1.6W0.8H0.8_Reflow]  (hidden comment: 885012206093)
C71  Cap_F: 47nF  [WCAP-CSGP_0603_L1.6W0.8H0.8_Reflow]  (hidden comment: 885012206093)
C72  VDC_V: 35V  ValueDisplayed: 10uF  [0805_HV]  (hidden comment: GRM21BR6YA106KE43L)
C73  Cap_F: 47nF  [WCAP-CSGP_0603_L1.6W0.8H0.8_Reflow]  (hidden comment: 885012206093)
C74  Cap_F: 100nF  VDC_V: 50V  [0603]  (hidden comment: GCM188R71H104KA57D)
C75  Cap_F: 100nF  VDC_V: 50V  [0603]  (hidden comment: GCM188R71H104KA57D)
C76  Cap_F: 100nF  VDC_V: 50V  [0603]  (hidden comment: GCM188R71H104KA57D)
C77  Cap_F: 1nF  [WCAP-CSGP_0603_L1.6W0.8H0.8_Reflow]  (hidden comment: 885012206059)
C78  Cap_F: 1nF  [WCAP-CSGP_0603_L1.6W0.8H0.8_Reflow]  (hidden comment: 885012206059)
C79  VDC_V: 50V  ValueDisplayed: 100pF  [0603]  (hidden comment: GRM1885C1H101JA01D)
C83  Cap_F: 1nF  [WCAP-CSGP_0603_L1.6W0.8H0.8_Reflow]  (hidden comment: 885012206059)
C84  Cap_F: 100nF  VDC_V: 50V  [0603]  (hidden comment: GCM188R71H104KA57D)
D8  value 18V  [SOD-323]  (hidden comment: MMSZ5248BS-7-F)
D9  value 18V  [SOD-323]  (hidden comment: MMSZ5248BS-7-F)
D10  value 18V  [SOD-323]  (hidden comment: MMSZ5248BS-7-F)
D11  value 18V  [SOD-323]  (hidden comment: MMSZ5248BS-7-F)
D12  BAT54T1G  [SOD-123]  (value not drawn)
R8  ValueDisplayed: 20.0  [0603]  (hidden comment: RC0603FR-0720RL)
R55  ValueDisplayed: 20.0  [0603]  (hidden comment: RC0603FR-0720RL)
R58  ValueDisplayed: 100  [0603]  (hidden comment: RC0603FR-07100RL)
R59  ValueDisplayed: 100  [0603]  (hidden comment: RC0603FR-07100RL)
R60  ValueDisplayed: 100  [0603]  (hidden comment: RC0603FR-07100RL)
R61  ValueDisplayed: 100  [0603]  (hidden comment: RC0603FR-07100RL)
R62  ValueDisplayed: 332k  [1206]  (hidden comment: RC1206FR-07332KL)
R63  ValueDisplayed: 332k  [1206]  (hidden comment: RC1206FR-07332KL)
R64  ValueDisplayed: 332k  [1206]  (hidden comment: RC1206FR-07332KL)
R65  ValueDisplayed: 100  [0603]  (hidden comment: RC0603FR-07100RL)
R66  ValueDisplayed: 100  [0603]  (hidden comment: RC0603FR-07100RL)
R67  ValueDisplayed: 332k  [1206]  (hidden comment: RC1206FR-07332KL)
R68  ValueDisplayed: 332k  [1206]  (hidden comment: RC1206FR-07332KL)
R69  ValueDisplayed: 332k  [1206]  (hidden comment: RC1206FR-07332KL)
R70  ValueDisplayed: 332k  [1206]  (hidden comment: RC1206FR-07332KL)
R71  ValueDisplayed: 332k  [1206]  (hidden comment: RC1206FR-07332KL)
R72  ValueDisplayed: 332k  [1206]  (hidden comment: RC1206FR-07332KL)
R73  ValueDisplayed: 0  [0603]  (hidden comment: RC0603JR-070RL)
R74  ValueDisplayed: 8.20k  [0603]  (hidden comment: RC0603FR-078K2L)
R75  ValueDisplayed: 8.20k  [0603]  (hidden comment: RC0603FR-078K2L)
R76  ValueDisplayed: 8.20k  [0603]  (hidden comment: RC0603FR-078K2L)
R77  ValueDisplayed: 1.00k  [0603]  (hidden comment: RC0603FR-071KL)
R78  ValueDisplayed: 10.0k  [0603]  (hidden comment: RC0603FR-0710KL)
R79  ValueDisplayed: 100  [0603]  (hidden comment: RC0603FR-07100RL)
R80  ValueDisplayed: 0.05  [CSRN2512]  (hidden comment: CSRN2512FT50L0)
R81  ValueDisplayed: 0.05  [CSRN2512]  (hidden comment: CSRN2512FT50L0)
R82  ValueDisplayed: 0.05  [CSRN2512]  (hidden comment: CSRN2512FT50L0)
R83  ValueDisplayed: 5.10k  [0603]  (hidden comment: RC0603FR-075K1L)
R85  ValueDisplayed: 20.0  [0603]  (hidden comment: RC0603FR-0720RL)
R87  ValueDisplayed: 5.10k  [0603]  (hidden comment: RC0603FR-075K1L)
R88  ValueDisplayed: 20.0  [0603]  (hidden comment: RC0603FR-0720RL)
R97  ValueDisplayed: 20.0  [0603]  (hidden comment: RC0603FR-0720RL)
R98  ValueDisplayed: 20.0  [0603]  (hidden comment: RC0603FR-0720RL)
R104  ValueDisplayed: 5.10k  [0603]  (hidden comment: RC0603FR-075K1L)
R105  ValueDisplayed: 5.10k  [0603]  (hidden comment: RC0603FR-075K1L)
R106  ValueDisplayed: 100  [0603]  (hidden comment: RC0603FR-07100RL)
R107  ValueDisplayed: 20.0k  [0603]  (hidden comment: RC0603FR-0720KL)
R108  ValueDisplayed: 1.00k  [0603]  (hidden comment: RC0603FR-071KL)
R109  ValueDisplayed: 20.0k  [0603]  (hidden comment: RC0603FR-0720KL)
RT1  TMP6131DECR  [DEC0002A]
U7  SLIMDIP-M  [FP-SLIMDIP-S_SLIMDIP-MFG]
U10  LMV331QDBVRQ1  [DBV0005A_L]

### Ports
DCBUS (in), IPM_FAULT (out), IPM_TEMP_AD (out), IU_N (out), IU_P (out), IV_N (out), IV_P (out), IW_N (out), IW_P (out), MOTOR_TEMP_AD (out), MOTOR_U (out), MOTOR_V (out), MOTOR_W (out), PWM_UH (in), PWM_UL (in), PWM_VH (in), PWM_VL (in), PWM_WH (in), PWM_WL (in), VU_AD (out), VV_AD (out), VW_AD (out)

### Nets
3.3V: C84.1 D12.1(K) R77.2 R78.1 R107.2 R109.1 U10.5(Vcc)
15V: R73.1
GND: C32.2 C59.2 C64.2 C65.2 C66.2 C67.2 C68.2 C69.2 C70.1 C71.1 C72.2 C73.1 C74.2 C75.2 C76.2 C77.1 C78.2 C79.2 C83.1 C84.2 D11.2(A) R74.1 R75.1 R76.1 R80.1 R81.1 R82.1 R83.1 R88.1 R97.1 R98.1 R108.1 RT1.1 U7.19(VNC) U10.2(GND)
VDCBUS: C59.1 U7.27(P) ; port DCBUS  [project net Ubus]
IPM_15V: C32.1 C72.1 C74.1 C75.1 D11.1(K) R73.2 U7.11(VP1) U7.16(VN1)
IPM_CIN: C83.2 R106.2 U7.18(CIN)
IPM_FAULT: C77.2 R79.1 ; port IPM_FAULT
IPM_PWM_UH: C64.1 R58.2 U7.8(UP)
IPM_PWM_UL: C65.1 R59.2 U7.13(UN)
IPM_PWM_VH: C66.1 R60.2 U7.9(VP)
IPM_PWM_VL: C67.1 R61.2 U7.14(VN)
IPM_PWM_WH: C68.1 R65.2 U7.10(WP)
IPM_PWM_WL: C69.1 R66.2 U7.15(WN)
IPM_TEMP_AD: C78.1 D12.2(A) R83.2 U7.20(VOT) ; port IPM_TEMP_AD
IU_N: C54.2 R97.2 ; port IU_N
IU_P: C54.1 R85.2 R87.1 ; port IU_P
IV_N: C31.2 R88.2 ; port IV_N
IV_P: C31.1 R55.2 R104.1 ; port IV_P
IW_N: C19.2 R98.2 ; port IW_N
IW_P: C19.1 R8.2 R105.1 ; port IW_P
MOTOR_TEMP_AD: C76.1 R77.1 RT1.2 ; port MOTOR_TEMP_AD
MOTOR_U: R62.2 U7.26(U) ; port MOTOR_U
MOTOR_V: R63.2 U7.25(V) ; port MOTOR_V
MOTOR_W: R64.2 U7.24(W) ; port MOTOR_W
PWM_UH: R58.1 ; port PWM_UH
PWM_UL: R59.1 ; port PWM_UL
PWM_VH: R60.1 ; port PWM_VH
PWM_VL: R61.1 ; port PWM_VL
PWM_WH: R65.1 ; port PWM_WH
PWM_WL: R66.1 ; port PWM_WL
VU_AD: C73.2 R70.1 R74.2 ; port VU_AD
VV_AD: C70.2 R71.1 R75.2 ; port VV_AD
VW_AD: C71.2 R72.1 R76.2 ; port VW_AD
NetC57_1: C57.1 C58.1 D8.2(A) U7.2(VUFS)
NetC57_2: C57.2 C58.2 D8.1(K) U7.3(VUFB)
NetC60_1: C60.1 C61.1 D9.2(A) U7.4(VVFS)
NetC60_2: C60.2 C61.2 D9.1(K) U7.5(VVFB)
NetC62_1: C62.1 C63.1 D10.2(A) U7.6(VWFS)
NetC62_2: C62.2 C63.2 D10.1(K) U7.7(VWFB)
NetC79_1: C79.1 R87.2 R104.2 R105.2 U10.1(IN+)
NetR8_1: R8.1 R80.2 U7.21(NW)
NetR55_1: R55.1 R81.2 U7.22(NV)
NetR62_1: R62.1 R67.2
NetR63_1: R63.1 R68.2
NetR64_1: R64.1 R69.2
NetR67_1: R67.1 R70.2
NetR68_1: R68.1 R71.2
NetR69_1: R69.1 R72.2
NetR78_2: R78.2 R79.2 U7.17(FO)
NetR82_2: R82.2 R85.1 U7.23(NU)
NetR106_1: R106.1 R109.2 U10.4(OUT)
NetR107_1: R107.1 R108.2 U10.3(IN-)

Not connected (* = marked no-connect by the designer): U7 12(VNC)*

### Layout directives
net class HV: Ubus
net class LV_Signal: 3.3V, 15V, GND, IPM_15V, IPM_CIN, IPM_PWM_UH, IPM_PWM_UL, IPM_PWM_VH, IPM_PWM_VL, IPM_PWM_WH, IPM_PWM_WL, IU_N, IU_P, IV_N, IV_P, IW_N, IW_P, MOTOR_U, MOTOR_V, MOTOR_W, VDCBUS

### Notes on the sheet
- INVERTER STAGE
- (near U10) 9.43A OCP

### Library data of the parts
C19 C31 C54 C78 = CMP-0104699-1: WCAP-CSGP Multilayer Ceramic Chip Capacitor, General Purpose, size 0603, X7R, 1nF, 25VDC; Manufacturer: Wurth Elektronik; Capacitance Tolerance: +/-10%; Case/Size Code: 0603; Dissipation Factor: 3.5%; Insulation Resistance: 10GOhm; Rated Voltage (DC): 25V; Technical Reference: X7R0603102K025DFCT10000
C32 C57 C60 C62 C72 = CMP-0008310-1: CAP, CERM, 10 uF, 35 V, +/- 10%, X5R, 0805; Manufacturer: MuRata; TaMin_C: -55°C; Polarized: N; SizeAreaWB_mm2: 6.75; Value1: Unknown; U/M: EA; Value: 10uF; TaMax_C: 85°C; SizeZ_mm: 1.45; SizeX_mm: 2; SizeY_mm: 1.25; Cap_Case: 0805; SizeArea_mm2: 2.5; Cap_F: 10µF; AEC Category: Q200
C58 C61 C63 C74-C76 C84 = CMP-0007144-4: as C36 on sheet MCU154A_Power
C59 = CMP-0012508-3: CAP, Film, 0.47 uF, 450 V, +/- 10%, TH; Manufacturer: Panasonic; TaMin_C: -40°C; Polarized: N; Value1: Unknown; Value: 0.47uF; TaMax_C: 110°C; Cap_Case: 12.6x6.5x12.7mm; Cap_F: 470nF; AEC Category: Q200
C64-C69 = CMP-0119384-1: WCAP-CSGP Multilayer Ceramic Chip Capacitor, General Purpose, size 0603, X7R, 220pF, 50VDC; Manufacturer: Wurth Elektronik; Capacitance Tolerance: +/-10%; Case/Size Code: 0603; Dissipation Factor: 2.5%; Insulation Resistance: 10GOhm; Rated Voltage (DC): 50V; Technical Reference: X7R0603221K050DFCT10000
C70 C71 C73 = CMP-0115476-1: as C56 on sheet MCU154A_Power
C77 C83 = CMP-0115442-1: WCAP-CSGP Multilayer Ceramic Chip Capacitor, General Purpose, size 0603, X7R, 1nF, 25VDC; Manufacturer: Wurth Elektronik; Capacitance Tolerance: +/-10%; Case/Size Code: 0603; Dissipation Factor: 3.5%; Insulation Resistance: 10GOhm; Rated Voltage (DC): 25V; Technical Reference: X7R0603102K025DFCT10000
C79 = CMP-0007171-4: as C48 on sheet MCU154A_Power
D8-D11 = CMP-0005835-4: as D6 on sheet MCU154A_Power
D12 = CMP-0028457-2: as D3 on sheet MCU154A_Power
R8 R55 R85 R88 R97 R98 = CMP-0022908-4: RES, 20.0, 1%, 0.1 W, 0603; Manufacturer: Yageo; Power_W: 100mW; TempCo: 100 ppm/C; Value_Code: 20R0; Value: 20.0; EIA_Code: E96; Res_ohm: 20; SizeX_mm: 1.6; SizeY_mm: 0.8; SizeZ_mm: 1; Value2: 0.1W; SizeArea_mm2: 1.28; AEC Qualified: N; VDC_V: 75V; AEC Category: Q200; SizeAreaWB_mm2: 4.68
R58-R61 R65 R66 R79 R106 = CMP-0022736-4: RES, 100, 1%, 0.1 W, 0603; Manufacturer: Yageo; Power_W: 100mW; TempCo: 100 ppm/C; Value_Code: 100R; Value: 100; EIA_Code: E96; SizeX_mm: 1.6; SizeY_mm: 0.8; SizeZ_mm: 1; Value2: 0.1W; SizeArea_mm2: 1.28; AEC Qualified: N; VDC_V: 75V; AEC Category: Q200; SizeAreaWB_mm2: 4.68
R62-R64 R67-R72 = CMP-0018207-2: as R47 on sheet MCU154A_Power
R73 = CMP-0025885-5: as R51 on sheet MCU154A_Power
R74-R76 = CMP-0023308-5: as R57 on sheet MCU154A_Power
R77 R108 = CMP-0022895-5: as R36 on sheet MCU154A_Power
R78 = CMP-0022746-5: as R38 on sheet MCU154A_Power
R80-R82 = CMP-0015791-2: RES, 0.05, 1%, 2 W, 2512; Manufacturer: Stackpole Electronics Inc; Power_W: 2W; TempCo: 200 ppm/C; Value_Code: R050; U/M: EA; Value: 0.05; EIA_Code: E96; Res_ohm: 50m; SizeX_mm: 6.35; SizeY_mm: 3.15; SizeZ_mm: 0.7; SizeArea_mm2: 20.0025; AEC Qualified: N; AEC Category: Q200
R83 R87 R104 R105 = CMP-0023198-5: RES, 5.10 k, 1%, 0.1 W, 0603; Manufacturer: Yageo; Power_W: 100mW; TempCo: 100 ppm/C; Value_Code: 5k10; Value: 5.10k; Res_ohm: 5.1k; SizeX_mm: 1.6; SizeY_mm: 0.8; SizeZ_mm: 1; Value2: 0.1W; SizeArea_mm2: 1.28; AEC Qualified: N; VDC_V: 75V; AEC Category: Q200; SizeAreaWB_mm2: 4.68
R107 R109 = CMP-0022906-5: as R46 on sheet MCU154A_Power
RT1 = CMP-0084566-1: Thermistor, DEC0002A (X1SON-2); Alternate Manufacturer: Texas Instruments; Alternate PartNumber: TMP6131DECT; CompType: IC; AEC Category: Q200; SizeX_mm: 1; AEC Qualified: N; SizeZ_mm: 0.5; SizeArea_mm2: 0.6; SizeAreaWB_mm2: 3.2
U7 = CMP-0033830-3: RC-IGBT inverter bridge for three phase DC-to-AC power conversion; Manufacturer: Mitsubishi Electric; SizeZ_mm: 6mm; AEC Qualified: No; Standoff Height: 1.4mm; TJmax_C: +150°C
U10 = CMP-0075716-1: GENERAL-PURPOSE LOW-VOLTAGE COMPARATOR, DBV0005A (SOT-23-5); Manufacturer: Texas Instruments; SizeAreaWB_mm2: 14.82; SizeArea_mm2: 8.12; SizeZ_mm: 1.45; SizeY_mm: 2.9; U/M: EA; CompType: IC; SizeX_mm: 2.8

## Sheet MCU154A_Interface.SchDoc: Interface
size A4; Date: Not shown in title block; ApprovedBy: Not shown in title block; CheckedBy: Not shown in title block; Author: Not shown in title block; CompanyName: Not shown in title block; DrawnBy: Hely Zhang; Engineer: Not shown in title block; Organization: Not shown in title block; Address1: Not shown in title block; Address2: Not shown in title block; Address3: Not shown in title block; Address4: Not shown in title block; DocumentNumber: 1; Revision: Use project parameter SCH_Rev; SheetNumber: 4; SheetTotal: 5; PageSetup: Record=PageOptions¦CenterHorizontal=True¦CenterVertical=True¦PrintScale=0.93¦XCorrection=1.00¦YCorrection=1.00¦PrintKind=0¦BorderSize=5000000¦LeftOffset=0¦BottomOffset=0¦Orientation=2¦PaperLength=1000¦PaperWidth=1000¦Scale=100¦PaperSource=15¦PrintQuality=600¦MediaType=1¦DitherType=10¦PaperKind=Letter¦PrintScaleMode=1
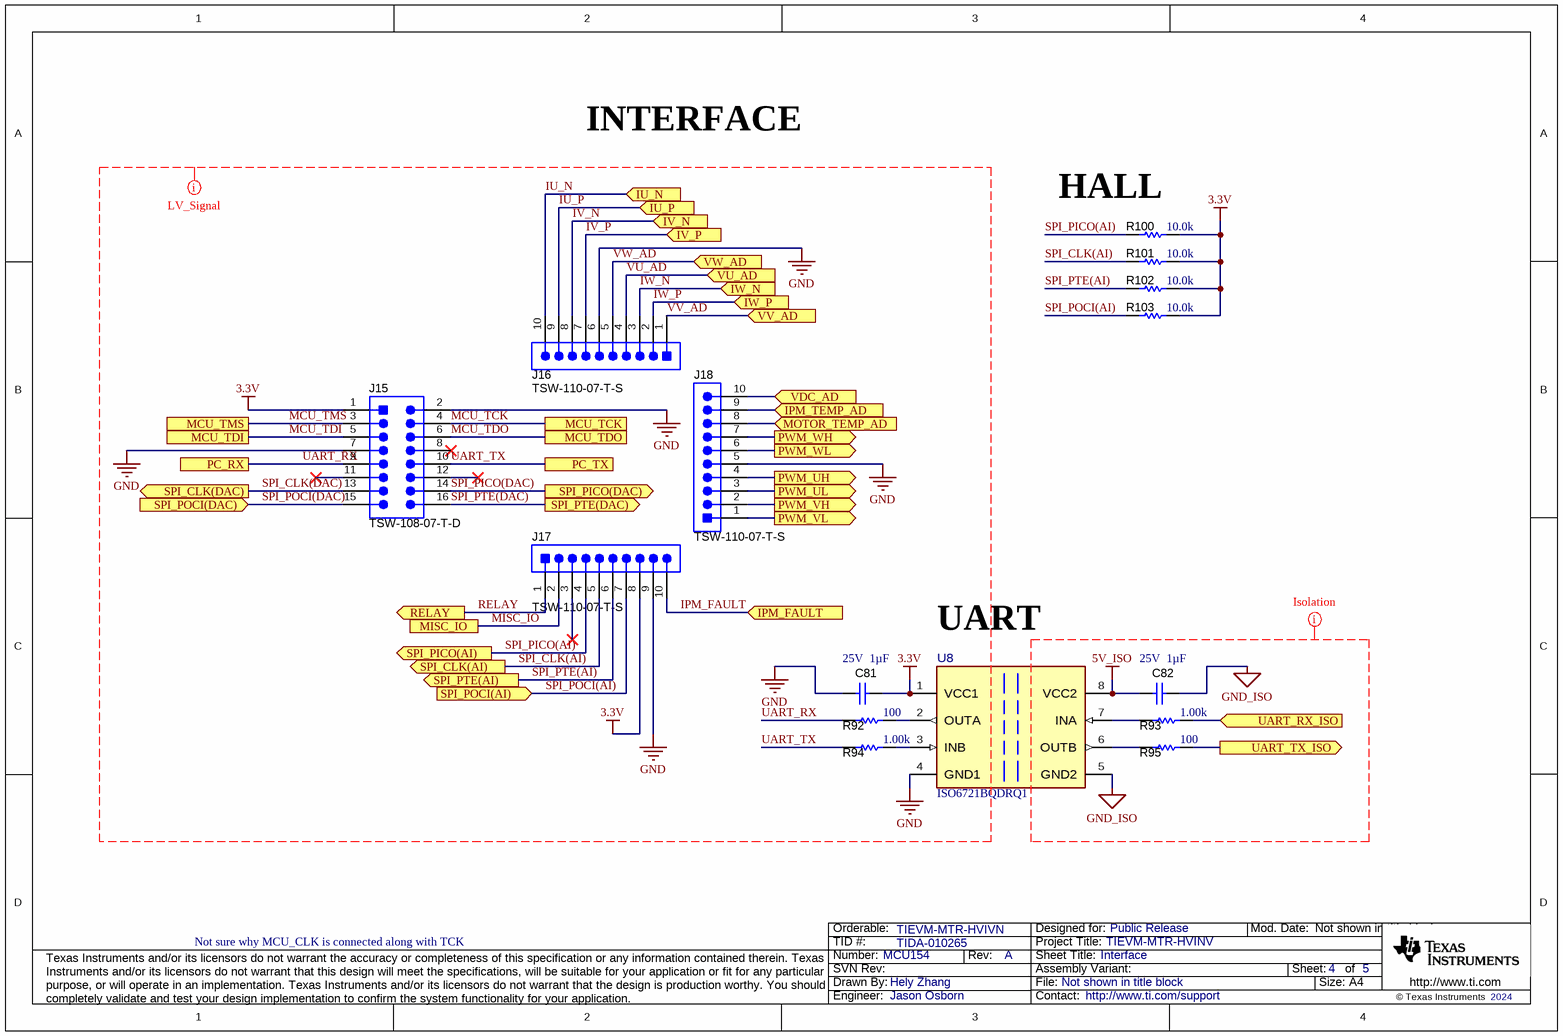
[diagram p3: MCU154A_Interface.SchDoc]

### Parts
C81  VDC_V: 25V  Cap_F: 1µF  [0603]  (hidden comment: CL10B105KA8NNNC)
C82  VDC_V: 25V  Cap_F: 1µF  [0603]  (hidden comment: CL10B105KA8NNNC)
J15  TSW-108-07-T-D  [FP-TSW-108-07-T-D_HDR16-MFG]
J16  TSW-110-07-T-S  [FP-TSW-110-07-T-S_HDR10-MFG]
J17  TSW-110-07-T-S  [FP-TSW-110-07-T-S_HDR10-MFG]
J18  TSW-110-07-T-S  [FP-TSW-110-07-T-S_HDR10-MFG]
R92  ValueDisplayed: 100  [0603]  (hidden comment: RC0603FR-07100RL)
R93  ValueDisplayed: 1.00k  [0603]  (hidden comment: RC0603FR-071KL)
R94  ValueDisplayed: 1.00k  [0603]  (hidden comment: RC0603FR-071KL)
R95  ValueDisplayed: 100  [0603]  (hidden comment: RC0603FR-07100RL)
R100  ValueDisplayed: 10.0k  [0603]  (hidden comment: RC0603FR-0710KL)
R101  ValueDisplayed: 10.0k  [0603]  (hidden comment: RC0603FR-0710KL)
R102  ValueDisplayed: 10.0k  [0603]  (hidden comment: RC0603FR-0710KL)
R103  ValueDisplayed: 10.0k  [0603]  (hidden comment: RC0603FR-0710KL)
U8  ISO6721BQDRQ1  [D0008A-MFG]

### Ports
IPM_FAULT (in), IPM_TEMP_AD (in), IU_N (in), IU_P (in), IV_N (in), IV_P (in), IW_N (in), IW_P (in), MCU_TCK, MCU_TDI, MCU_TDO, MCU_TMS, MISC_IO, MOTOR_TEMP_AD (in), PC_RX, PC_TX, PWM_UH (out), PWM_UL (out), PWM_VH (out), PWM_VL (out), PWM_WH (out), PWM_WL (out), RELAY (out), SPI_CLK(AI) (out), SPI_CLK(DAC) (out), SPI_PICO(AI) (out), SPI_PICO(DAC) (out), SPI_POCI(AI) (in), SPI_POCI(DAC) (in), SPI_PTE(AI) (out), SPI_PTE(DAC) (out), UART_RX_ISO (in), UART_TX_ISO (out), VDC_AD (in), VU_AD (in), VV_AD (in), VW_AD (in)

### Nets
3.3V: C81.2 J15.1 J17.8 R100.1 R101.1 R102.1 R103.1 U8.1(VCC1)
5V_ISO: C82.1 U8.8(VCC2)
GND: C81.1 J15.2 J15.7 J16.6 J17.9 J18.5 U8.4(GND1)
GND_ISO: C82.2 U8.5(GND2)
IPM_FAULT: J17.10 ; port IPM_FAULT
IPM_TEMP_AD: J18.9 ; port IPM_TEMP_AD
IU_N: J16.10 ; port IU_N
IU_P: J16.9 ; port IU_P
IV_N: J16.8 ; port IV_N
IV_P: J16.7 ; port IV_P
IW_N: J16.3 ; port IW_N
IW_P: J16.2 ; port IW_P
MCU_TCK: J15.4 ; port MCU_TCK
MCU_TDI: J15.5 ; port MCU_TDI
MCU_TDO: J15.6 ; port MCU_TDO
MCU_TMS: J15.3 ; port MCU_TMS
MISC_IO: J17.2 ; port MISC_IO
MOTOR_TEMP_AD: J18.8 ; port MOTOR_TEMP_AD
PWM_UH: J18.4 ; port PWM_UH
PWM_UL: J18.3 ; port PWM_UL
PWM_VH: J18.2 ; port PWM_VH
PWM_VL: J18.1 ; port PWM_VL
PWM_WH: J18.7 ; port PWM_WH
PWM_WL: J18.6 ; port PWM_WL
RELAY: J17.1 ; port RELAY
SPI_CLK(AI): J17.5 R101.2 ; port SPI_CLK(AI)
SPI_CLK(DAC): J15.13 ; port SPI_CLK(DAC)
SPI_PICO(AI): J17.4 R100.2 ; port SPI_PICO(AI)
SPI_PICO(DAC): J15.14 ; port SPI_PICO(DAC)
SPI_POCI(AI): J17.7 R103.2 ; port SPI_POCI(AI)
SPI_POCI(DAC): J15.15 ; port SPI_POCI(DAC)
SPI_PTE(AI): J17.6 R102.2 ; port SPI_PTE(AI)
SPI_PTE(DAC): J15.16 ; port SPI_PTE(DAC)
UART_RX: J15.9 R92.1 ; port PC_RX
UART_RX_ISO: R93.2 ; port UART_RX_ISO
UART_TX: J15.10 R94.1 ; port PC_TX
UART_TX_ISO: R95.2 ; port UART_TX_ISO
VDC_AD: J18.10 ; port VDC_AD
VU_AD: J16.4 ; port VU_AD
VV_AD: J16.1 ; port VV_AD
VW_AD: J16.5 ; port VW_AD
NetR92_2: R92.2 U8.2(OUTA)
NetR93_1: R93.1 U8.7(INA)
NetR94_2: R94.2 U8.3(INB)
NetR95_1: R95.1 U8.6(OUTB)

Not connected (* = marked no-connect by the designer): J15 8* 11* 12*; J17 3*

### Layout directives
net class LV_Signal: 3.3V, 5V_ISO, GND, GND_ISO, IPM_FAULT, IU_N, IU_P, IV_N, IV_P, IW_N, IW_P, MCU_TCK, MCU_TDI, MCU_TDO, MCU_TMS, MISC_IO, RELAY, SPI_CLK(AI), SPI_CLK(DAC), SPI_PICO(AI), SPI_PICO(DAC), SPI_POCI(AI), SPI_POCI(DAC), SPI_PTE(AI), SPI_PTE(DAC), UART_RX, UART_TX, VU_AD, VV_AD, VW_AD

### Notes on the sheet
- INTERFACE
- (near R100) HALL
- UART
- Not sure why MCU_CLK is connected along with TCK

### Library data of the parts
C81 C82 = CMP-0086540-3: CAP, 1uF, 25V, ±10%, X7R, 0603; Manufacturer: Samsung; TempCo: 15%; AEC Qualified: No; SizeZ_mm: 0.9mm; Symbol Name: SYM-CL10B105KA8NNNC
J15 = CMP-0123024-2: Connector Header Through Hole 16 position 0.100" (2.54mm); Manufacturer: Samtec; ContactFinish: Tin,Nickel; Row_Count: 2; AEC Qualified: No; Category 0836C53C3D42D3F1: Connectors; Category 75Fab8F04590Ae3D: Connectors and Adapters; Category A3C16Ecb93907806: Uncategorized; Category E7012A0Bd22E3Cc6: Headers & Receptacles; Conn Gender: Male; Conn Orientation: Vertical; SizeZ_mm: 8.71mm
J16-J18 = CMP-0123044-2: Conn Unshrouded Header HDR 10 POS 2.54mm Solder ST Top Entry Thru-Hole Bag; Manufacturer: Samtec; ContactFinish: Tin,Nickel; Row_Count: 1; AEC Qualified: No; Category 0836C53C3D42D3F1: Connectors; Category 75Fab8F04590Ae3D: Connectors and Adapters; Category A3C16Ecb93907806: Uncategorized; Category E7012A0Bd22E3Cc6: Headers & Receptacles; Conn Gender: Male; Conn Orientation: Vertical; SizeZ_mm: 8.71mm
R92 R95 = CMP-0022736-4: as R58 on sheet MCU154A_IPM
R93 R94 = CMP-0022895-5: as R36 on sheet MCU154A_Power
R100-R103 = CMP-0022746-5: as R38 on sheet MCU154A_Power
U8 = CMP-0089949-1: Low Speed, General Purpose, Robust EMC, Dual-Channel Digital Isolators; Manufacturer: Texas Instruments; TJmax_C: +150°C; TaMin_C: -40°C; SizeZ_mm: 1.75mm; Min Supply Voltage: 1.71V; Standoff Height: 0.11mm; AEC Qualified: Yes; TaMax_C: +125°C; AEC Grade: Grade 1; Max Supply Voltage: 5.5V; Interface: LVCMOS

## Sheet MCU154A_Hardware.SchDoc: Hardware
size A4; Date: Not shown in title block; ApprovedBy: Not shown in title block; CheckedBy: Not shown in title block; Author: Not shown in title block; CompanyName: Not shown in title block; DrawnBy: Hely Zhang; Engineer: Not shown in title block; Organization: Not shown in title block; Address1: Not shown in title block; Address2: Not shown in title block; Address3: Not shown in title block; Address4: Not shown in title block; DocumentNumber: 3; Revision: Use project parameter SCH_Rev; SheetNumber: 5; SheetTotal: 5; PageSetup: Record=PageOptions¦CenterHorizontal=True¦CenterVertical=True¦PrintScale=1.00¦XCorrection=1.00¦YCorrection=1.00¦PrintKind=0¦BorderSize=5000000¦LeftOffset=0¦BottomOffset=0¦Orientation=2¦PaperLength=1000¦PaperWidth=1000¦Scale=100¦PaperSource=15¦PrintQuality=600¦MediaType=1¦DitherType=10¦PaperKind=Letter¦PrintScaleMode=1
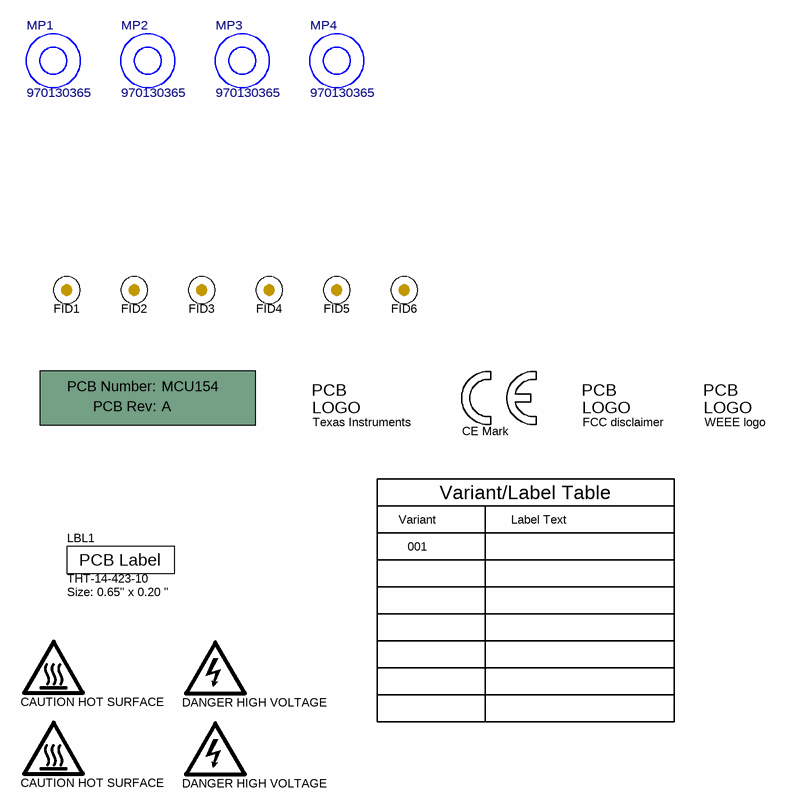
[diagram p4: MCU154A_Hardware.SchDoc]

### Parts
!PCB1  Printed Circuit Board  (value not drawn)  (mechanical)
FID1  Fiducial  [Fiducial10-20]  (value not drawn)
FID2  Fiducial  [Fiducial10-20]  (value not drawn)
FID3  Fiducial  [Fiducial10-20]  (value not drawn)
FID4  Fiducial  [Fiducial10-20]  (value not drawn)
FID5  Fiducial  [Fiducial10-20]  (value not drawn)
FID6  Fiducial  [Fiducial10-20]  (value not drawn)
LBL1  THT-14-423-10  Note: Size: 0.65" x 0.20 "  [Label_650x200]
Logo1  CE Mark  [CE_Mark_5mm]  (no BOM)
Logo2  Texas Instruments  [TI_Symbol_Overlay_Small]  (no BOM)
Logo3  FCC disclaimer  [FCC_disclaimer]  (no BOM)
Logo4  WEEE logo  [WEEE_Minimum]  (no BOM)
LOGO5  CAUTION HOT SURFACE  [IEC_HotSurface_Small]  (no BOM)
LOGO6  DANGER HIGH VOLTAGE  [IEC_HighVoltage_Small]  (no BOM)
LOGO7  CAUTION HOT SURFACE  [IEC_HotSurface_Small]  (no BOM)
LOGO8  DANGER HIGH VOLTAGE  [IEC_HighVoltage_Small]  (no BOM)
MP1  970130365  [FP-970130365_SPCAER_M3-MFG]
MP2  970130365  [FP-970130365_SPCAER_M3-MFG]
MP3  970130365  [FP-970130365_SPCAER_M3-MFG]
MP4  970130365  [FP-970130365_SPCAER_M3-MFG]

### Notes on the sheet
- Variant
- Variant/Label Table
- Label Text
- 001

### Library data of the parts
!PCB1 = CMP-0003618-2: Manufacturer: Any; PartNumber: MCU154
FID1-FID6 = CMP-0077181-1: Fiducial mark.  There is nothing to buy or mount.
LBL1 = CMP-0003625-1: Thermal Transfer Printable Labels, 0.650" W x 0.200" H - 10,000 per roll; Manufacturer: Brady; CompType: Label
Logo1 = CMP-0074844-1: SymbolCreator: a0412235
Logo2 = CMP-0074838-1: Texas Instrument Corporate Signature; SymbolCreator: a0412235; Lib Reference: TI_Logo; Library Reference: Logo
Logo3 = CMP-0074847-1: FCC_disclaimer; Library Reference: Logo
Logo4 = CMP-0074769-1
LOGO5 LOGO7 = CMP-0074837-1: IEC 61010-1 Hot Surface Warning; SymbolCreator: a0412235; Lib Reference: IEC_HotSurface
LOGO6 LOGO8 = CMP-0074835-1: IEC 61010-1 High Voltage Warning; SymbolCreator: a0412235; Lib Reference: IEC_HighVoltage
MP1-MP4 = CMP-0087151-1: Manufacturer: Wurth Electronics

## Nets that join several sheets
3.3V: MCU154A_Power (5 pins), MCU154A_IPM (7 pins), MCU154A_Interface (8 pins)
5V_ISO: MCU154A_Main (J14.4), MCU154A_Interface (C82.1 U8.8)
15V: MCU154A_Power (11 pins), MCU154A_IPM (R73.1)
EGND: MCU154A_Main (J5.3), MCU154A_Power (C33.2 C40.1)
GND: MCU154A_Power (27 pins), MCU154A_IPM (35 pins), MCU154A_Interface (7 pins)
GND_ISO: MCU154A_Main (J14.1), MCU154A_Interface (C82.2 U8.5)
Ubus: MCU154A_Power (7 pins), MCU154A_IPM (C59.1 U7.27)
IPM_FAULT: MCU154A_IPM (C77.2 R79.1), MCU154A_Interface (J17.10)
IPM_TEMP_AD: MCU154A_IPM (C78.1 D12.2 R83.2 U7.20), MCU154A_Interface (J18.9)
IU_N: MCU154A_IPM (C54.2 R97.2), MCU154A_Interface (J16.10)
IU_P: MCU154A_IPM (C54.1 R85.2 R87.1), MCU154A_Interface (J16.9)
IV_N: MCU154A_IPM (C31.2 R88.2), MCU154A_Interface (J16.8)
IV_P: MCU154A_IPM (C31.1 R55.2 R104.1), MCU154A_Interface (J16.7)
IW_N: MCU154A_IPM (C19.2 R98.2), MCU154A_Interface (J16.3)
IW_P: MCU154A_IPM (C19.1 R8.2 R105.1), MCU154A_Interface (J16.2)
LINE: MCU154A_Main (J5.1), MCU154A_Power (XF1.1 XF1.2)
MOTOR_TEMP_AD: MCU154A_IPM (C76.1 R77.1 RT1.2), MCU154A_Interface (J18.8)
MOTOR_U: MCU154A_Main (J10.1), MCU154A_IPM (R62.2 U7.26)
MOTOR_V: MCU154A_Main (J10.2), MCU154A_IPM (R63.2 U7.25)
MOTOR_W: MCU154A_Main (J10.3), MCU154A_IPM (R64.2 U7.24)
NEU: MCU154A_Main (J5.2), MCU154A_Power (C34.2 L2.4 R42.1)
PWM_UH: MCU154A_IPM (R58.1), MCU154A_Interface (J18.4)
PWM_UL: MCU154A_IPM (R59.1), MCU154A_Interface (J18.3)
PWM_VH: MCU154A_IPM (R60.1), MCU154A_Interface (J18.2)
PWM_VL: MCU154A_IPM (R61.1), MCU154A_Interface (J18.1)
PWM_WH: MCU154A_IPM (R65.1), MCU154A_Interface (J18.7)
PWM_WL: MCU154A_IPM (R66.1), MCU154A_Interface (J18.6)
RELAY: MCU154A_Power (R36.1), MCU154A_Interface (J17.1)
UART_RX_ISO: MCU154A_Main (J14.3), MCU154A_Interface (R93.2)
UART_TX_ISO: MCU154A_Main (J14.2), MCU154A_Interface (R95.2)
VDC_AD: MCU154A_Power (C56.2 R54.1 R57.2), MCU154A_Interface (J18.10)
VU_AD: MCU154A_IPM (C73.2 R70.1 R74.2), MCU154A_Interface (J16.4)
VV_AD: MCU154A_IPM (C70.2 R71.1 R75.2), MCU154A_Interface (J16.1)
VW_AD: MCU154A_IPM (C71.2 R72.1 R76.2), MCU154A_Interface (J16.5)

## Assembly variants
001: not fitted FID1 FID2 FID3 FID4 FID5 FID6 LBL1 MP1 MP2 MP3 MP4 R51 R56 R92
